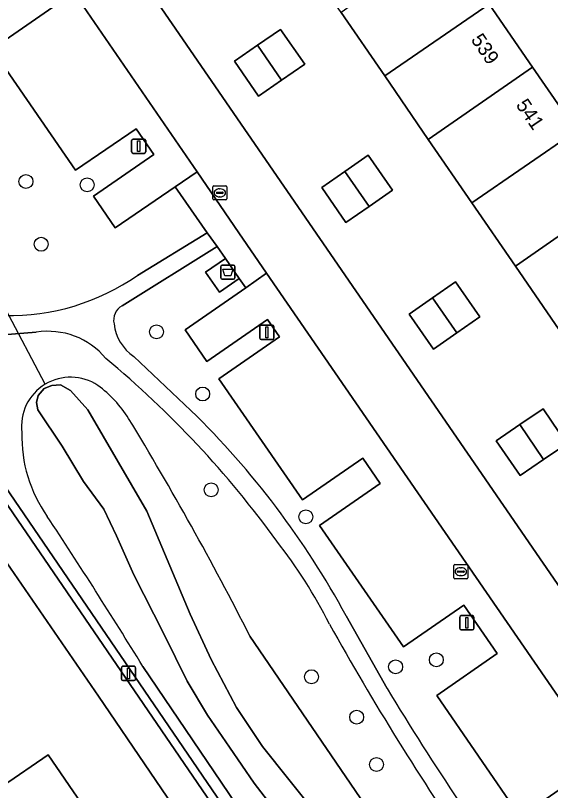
# Model space of a CAD drawing. Extents: x 155275 to 156265, y 382654 to 383635.
# Drawn here: x 155728.7 to 155766.3, y 383458.9 to 383513.4 of the extents above; entities that cross this region are included whole.
import ezdxf

# ---------------------------------------------------------------- set-up
doc = ezdxf.new("R2010")
doc.units = 0
for name, color, linetype in [('IMGEO_Afval_apart_plaats', 7, 'Continuous'), ('IMGEO_Boom', 7, 'Continuous'), ('IMGEO_Duiker', 7, 'Continuous'), ('IMGEO_Erf', 7, 'Continuous'), ('IMGEO_Groenvoorziening', 7, 'Continuous'), ('IMGEO_Haag', 7, 'Continuous'), ('IMGEO_Lichtmast', 7, 'Continuous'), ('IMGEO_Oever', 7, 'Continuous'), ('IMGEO_Pand', 7, 'Continuous'), ('IMGEO_Pand_nummerreeks', 7, 'Continuous'), ('IMGEO_Parkeervlak_halfverhard', 7, 'Continuous'), ('IMGEO_Parkeervlak_open', 7, 'Continuous'), ('IMGEO_Rijbaan_lokaal_open', 7, 'Continuous'), ('IMGEO_Rioolput', 7, 'Continuous'), ('IMGEO_Voetpad_gesloten', 7, 'Continuous'), ('IMGEO_Voetpad_halfverhard', 7, 'Continuous'), ('IMGEO_Voetpad_open', 7, 'Continuous'), ('IMGEO_Waterloop', 7, 'Continuous')]:
    doc.layers.add(name, color=color, linetype=linetype)

msp = doc.modelspace()

# ---------------------------------------------------------------- linework, layer by layer
at = {"layer": 'IMGEO_Afval_apart_plaats'}
for p, q in [((155743.118, 383494.938), (155743.118, 383495.738)), ((155743.118, 383495.738), (155743.118, 383494.938)), ((155743.218, 383495.838), (155744.008, 383495.838)), ((155744.008, 383495.838), (155743.218, 383495.838)), ((155744.108, 383495.738), (155744.108, 383494.938)), ((155744.108, 383494.938), (155744.108, 383495.738)), ((155744.008, 383494.838), (155743.218, 383494.838)), ((155743.218, 383494.838), (155744.008, 383494.838))]:
    msp.add_line(p, q, dxfattribs=at)
msp.add_lwpolyline([(155743.261, 383495.552), (155743.965, 383495.552), (155743.816, 383495.082), (155743.41, 383495.082), (155743.261, 383495.552)], dxfattribs=at)
for centre, start, end in [((155743.218, 383495.738), 90, 180), ((155743.218, 383495.738), 90, 180), ((155744.008, 383495.738), 0, 90), ((155744.008, 383495.738), 360, 90), ((155743.218, 383494.938), 180, 270), ((155743.218, 383494.938), 180, 270), ((155744.008, 383494.938), 270, 0), ((155744.008, 383494.938), 270, 0)]:
    msp.add_arc(centre, 0.1, start, end, dxfattribs=at)
at = {"layer": 'IMGEO_Boom'}
for centre in [(155729.423, 383501.706), (155733.72, 383501.473), (155730.493, 383497.298), (155738.596, 383491.15), (155741.843, 383486.78), (155742.438, 383480.043), (155749.094, 383478.147), (155758.263, 383468.099), (155755.398, 383467.613), (155749.484, 383466.913), (155752.66, 383464.077), (155754.055, 383460.748)]:
    msp.add_circle(centre, 0.489, dxfattribs=at)
at = {"layer": 'IMGEO_Duiker'}
msp.add_lwpolyline([(155730.77, 383487.457), (155725.166, 383498.045)], dxfattribs=at)
at = {"layer": 'IMGEO_Erf'}
msp.add_lwpolyline([(155726.768, 383531.573), (155770.822, 383467.542), (155779.252, 383473.301), (155776.091, 383477.9), (155773.031, 383482.352), (155769.971, 383486.803), (155766.894, 383491.28), (155763.817, 383495.756), (155760.755, 383500.211), (155757.693, 383504.666), (155754.631, 383509.121), (155751.569, 383513.576), (155748.535, 383517.99), (155745.501, 383522.404), (155742.436, 383526.863), (155739.371, 383531.322), (155736.332, 383535.743), (155733.649, 383539.647), (155733.271, 383540.147), (155733.075, 383540.407), (155735.571, 383542.155), (155732.704, 383546.343), (155729.619, 383550.85), (155725.564, 383556.774)], dxfattribs=at)
for points in [[(155747.387, 383508.831), (155745.762, 383507.702), (155744.073, 383510.172), (155745.69, 383511.275), (155747.305, 383512.376), (155749.012, 383509.959)], [(155753.539, 383499.957), (155751.908, 383498.824), (155750.211, 383501.295), (155751.83, 383502.419), (155753.461, 383503.552), (155755.171, 383501.09)], [(155759.691, 383491.065), (155758.058, 383489.93), (155756.35, 383492.389), (155757.982, 383493.524), (155759.615, 383494.659), (155761.324, 383492.2)], [(155765.763, 383485.74), (155767.434, 383483.282), (155765.797, 383482.169), (155764.159, 383481.056), (155762.464, 383483.496), (155764.126, 383484.627)], [(155734.512, 383465.559), (155725.215, 383479.049), (155698.054, 383460.537), (155694.998, 383458.429), (155719.873, 383421.949), (155720.07, 383422.058), (155723.062, 383417.667), (155735.929, 383398.789), (155735.874, 383398.763), (155746.045, 383383.83), (155750.929, 383387.164), (155776.093, 383404.417), (155774.449, 383406.803)], [(155717.664, 383447.195), (155717.921, 383446.826), (155717.566, 383446.593), (155710.254, 383441.58), (155707.639, 383445.383), (155714.926, 383450.427), (155730.979, 383461.428), (155735.677, 383454.594), (155724.14, 383446.672), (155721.829, 383450.056)]]:
    msp.add_lwpolyline(points, close=True, dxfattribs=at)
at = {"layer": 'IMGEO_Groenvoorziening'}
for points in [[(155727.024, 383511.005), (155731.306, 383513.946), (155729.557, 383516.497), (155725.308, 383513.54)], [(155737.252, 383495.109), (155742.155, 383498.108), (155739.9, 383501.331), (155735.683, 383498.451), (155734.166, 383500.672), (155738.404, 383503.602), (155737.163, 383505.396), (155732.916, 383502.493), (155727.024, 383511.005)], [(155754.325, 383480.486), (155753.102, 383482.269), (155748.849, 383479.332), (155742.968, 383487.853), (155747.233, 383490.798), (155746.401, 383492.022), (155742.127, 383489.072), (155740.605, 383491.282), (155744.87, 383494.241), (155744.414, 383494.898), (155743.017, 383493.929), (155742.048, 383495.326), (155743.444, 383496.295), (155742.863, 383497.137), (155736.184, 383492.976)], [(155730.153, 383491.12), (155722.598, 383490.514)], [(155720.532, 383490.035), (155723.759, 383485.312), (155724.227, 383485.725), (155777.645, 383407.499), (155785.035, 383418.096), (155785.37, 383418.576), (155786.992, 383420.901), (155789.946, 383428.782), (155786.989, 383433.092)], [(155737, 383489.423), (155741.017, 383485.615)], [(155786.215, 383434.22), (155781.307, 383441.344), (155778.247, 383445.759), (155773.985, 383442.8), (155772.453, 383445.011), (155776.691, 383447.968), (155775.493, 383449.71), (155771.239, 383446.769), (155765.386, 383455.301), (155769.624, 383458.239), (155768.412, 383460.022), (155764.146, 383457.078), (155758.294, 383465.605), (155762.537, 383468.543), (155760.192, 383471.953), (155755.953, 383469.016), (155750.056, 383477.55), (155754.325, 383480.486)], [(155751.926, 383471.183), (155754.811, 383466.087)], [(155745.162, 383469.764), (155752.897, 383458.412), (155764.88, 383444.182)], [(155753.217, 383444.635), (155737.64, 383467.64)]]:
    msp.add_lwpolyline(points, dxfattribs=at)
msp.add_lwpolyline([(155724.227, 383485.725), (155723.759, 383485.312), (155746.216, 383452.521), (155760.092, 383432.137), (155777.308, 383407.016), (155777.645, 383407.499)], close=True, dxfattribs=at)
for centre, radius, start, end in [((155728.247, 383508.029), 15.748, 268.8306, 304.8743), ((155736.735, 383491.963), 1.153, 118.5523, 192.8797), ((155738.762, 383492.059), 3.171, 186.3961, 236.2374), ((155730.972, 383485.896), 5.288, 39.7057, 98.9075), ((155690.152, 383435.237), 70.25, 35.90812, 50.28401), ((155732.561, 383484.511), 3.448, 56.2302, 121.2979), ((155732.545, 383484.515), 3.436, 121.0979, 187.4751), ((155729.684, 383480.764), 8.168, 31.6081, 54.0592), ((155699.071, 383442.569), 60.103, 28.42935, 45.74117), ((155548.166, 383369.919), 220.854, 26.87763, 31.41796), ((155738.86, 383483.789), 9.726, 178.3567, 215.206), ((155426.84, 383276.731), 364.751, 31.56029, 33.52476), ((155719.453, 383454.82), 35.056, 26.7787, 38.072), ((155923.166, 383566.527), 197.298, 209.08671, 214.6002), ((155914.464, 383561.979), 186.238, 210.9903, 213.8953)]:
    msp.add_arc(centre, radius, start, end, dxfattribs=at)
at = {"layer": 'IMGEO_Haag'}
msp.add_lwpolyline([(155724.227, 383485.725), (155723.759, 383485.312), (155746.216, 383452.521), (155760.092, 383432.137), (155777.308, 383407.016), (155777.645, 383407.499)], close=True, dxfattribs=at)
at = {"layer": 'IMGEO_Lichtmast'}
for p, q in [((155736.949, 383504.681), (155737.739, 383504.681)), ((155737.739, 383504.681), (155736.949, 383504.681)), ((155736.849, 383503.781), (155736.849, 383504.581)), ((155736.849, 383504.581), (155736.849, 383503.781)), ((155737.839, 383504.581), (155737.839, 383503.781)), ((155737.839, 383503.781), (155737.839, 383504.581)), ((155737.739, 383503.681), (155736.949, 383503.681)), ((155736.949, 383503.681), (155737.739, 383503.681)), ((155745.854, 383490.71), (155745.854, 383491.51)), ((155745.854, 383491.51), (155745.854, 383490.71)), ((155745.954, 383491.61), (155746.744, 383491.61)), ((155746.744, 383491.61), (155745.954, 383491.61)), ((155746.844, 383491.51), (155746.844, 383490.71)), ((155746.844, 383490.71), (155746.844, 383491.51)), ((155746.744, 383490.61), (155745.954, 383490.61)), ((155745.954, 383490.61), (155746.744, 383490.61)), ((155759.915, 383470.305), (155759.915, 383471.105)), ((155759.915, 383471.105), (155759.915, 383470.305)), ((155760.015, 383471.205), (155760.805, 383471.205)), ((155760.805, 383471.205), (155760.015, 383471.205)), ((155760.905, 383471.105), (155760.905, 383470.305)), ((155760.905, 383470.305), (155760.905, 383471.105)), ((155760.805, 383470.205), (155760.015, 383470.205)), ((155760.015, 383470.205), (155760.805, 383470.205)), ((155736.135, 383466.749), (155736.135, 383467.549)), ((155736.135, 383467.549), (155736.135, 383466.749)), ((155736.235, 383467.649), (155737.025, 383467.649)), ((155737.025, 383467.649), (155736.235, 383467.649)), ((155737.125, 383467.549), (155737.125, 383466.749)), ((155737.125, 383466.749), (155737.125, 383467.549)), ((155737.025, 383466.649), (155736.235, 383466.649)), ((155736.235, 383466.649), (155737.025, 383466.649))]:
    msp.add_line(p, q, dxfattribs=at)
for points in [[(155737.269, 383504.556), (155737.419, 383504.556), (155737.419, 383503.806), (155737.269, 383503.806), (155737.269, 383504.556)], [(155746.274, 383491.485), (155746.424, 383491.485), (155746.424, 383490.735), (155746.274, 383490.735), (155746.274, 383491.485)], [(155760.335, 383471.08), (155760.485, 383471.08), (155760.485, 383470.33), (155760.335, 383470.33), (155760.335, 383471.08)], [(155736.555, 383467.524), (155736.705, 383467.524), (155736.705, 383466.774), (155736.555, 383466.774), (155736.555, 383467.524)]]:
    msp.add_lwpolyline(points, dxfattribs=at)
for centre, start, end in [((155736.949, 383504.581), 90, 180), ((155736.949, 383504.581), 90, 180), ((155737.739, 383504.581), 0, 90), ((155737.739, 383504.581), 360, 90), ((155736.949, 383503.781), 180, 270), ((155736.949, 383503.781), 180, 270), ((155737.739, 383503.781), 270, 0), ((155737.739, 383503.781), 270, 0), ((155745.954, 383491.51), 90, 180), ((155745.954, 383491.51), 90, 180), ((155746.744, 383491.51), 0, 90), ((155746.744, 383491.51), 360, 90), ((155745.954, 383490.71), 180, 270), ((155745.954, 383490.71), 180, 270), ((155746.744, 383490.71), 270, 0), ((155746.744, 383490.71), 270, 0), ((155760.015, 383471.105), 90, 180), ((155760.015, 383471.105), 90, 180), ((155760.805, 383471.105), 0, 90), ((155760.805, 383471.105), 360, 90), ((155760.015, 383470.305), 180, 270), ((155760.015, 383470.305), 180, 270), ((155760.805, 383470.305), 270, 0), ((155760.805, 383470.305), 270, 0), ((155736.235, 383467.549), 90, 180), ((155736.235, 383467.549), 90, 180), ((155737.025, 383467.549), 0, 90), ((155737.025, 383467.549), 360, 90), ((155736.235, 383466.749), 180, 270), ((155736.235, 383466.749), 180, 270), ((155737.025, 383466.749), 270, 0), ((155737.025, 383466.749), 270, 0)]:
    msp.add_arc(centre, 0.1, start, end, dxfattribs=at)
at = {"layer": 'IMGEO_Oever'}
for points in [[(155747.4, 383456.9), (155745.459, 383459.436), (155743.726, 383461.969), (155742.18, 383464.212), (155740.744, 383466.604), (155739.117, 383469.921), (155737.012, 383474.068), (155735.783, 383476.82), (155734.887, 383478.68), (155733.465, 383480.622), (155731.966, 383483.107), (155730.261, 383485.654), (155730.163, 383486.184), (155730.287, 383486.675), (155730.71, 383487.175), (155731.243, 383487.38), (155731.851, 383487.412), (155732.544, 383487.027), (155733.778, 383485.676), (155737.922, 383478.547), (155740.965, 383471.317), (155742.429, 383468.117), (155744.212, 383464.754), (155746.049, 383462.013), (155749.851, 383457.256)], [(155764.88, 383444.182), (155752.897, 383458.412), (155745.162, 383469.764)], [(155737.64, 383467.64), (155753.217, 383444.635)]]:
    msp.add_lwpolyline(points, dxfattribs=at)
for centre, radius, start, end in [((155732.561, 383484.511), 3.448, 56.2302, 121.2979), ((155732.545, 383484.515), 3.436, 121.0979, 187.4751), ((155729.684, 383480.764), 8.168, 31.6081, 54.0592), ((155548.166, 383369.919), 220.854, 26.87763, 31.41796), ((155738.86, 383483.789), 9.726, 178.3567, 215.206), ((155426.84, 383276.731), 364.751, 31.56029, 33.52476)]:
    msp.add_arc(centre, radius, start, end, dxfattribs=at)
at = {"layer": 'IMGEO_Pand'}
for points in [[(155761.966, 383514.163), (155758.836, 383518.709), (155751.569, 383513.576), (155754.631, 383509.121)], [(155765.007, 383509.747), (155761.966, 383514.163), (155754.631, 383509.121), (155757.693, 383504.666)], [(155747.305, 383512.376), (155745.69, 383511.275), (155747.387, 383508.831), (155749.012, 383509.959)], [(155745.69, 383511.275), (155744.073, 383510.172), (155745.762, 383507.702), (155747.387, 383508.831)], [(155768.098, 383505.258), (155765.007, 383509.747), (155757.693, 383504.666), (155760.755, 383500.211)], [(155771.137, 383500.844), (155768.098, 383505.258), (155760.755, 383500.211), (155763.817, 383495.756)], [(155753.461, 383503.552), (155751.83, 383502.419), (155753.539, 383499.957), (155755.171, 383501.09)], [(155751.83, 383502.419), (155750.211, 383501.295), (155751.908, 383498.824), (155753.539, 383499.957)], [(155774.244, 383496.332), (155771.137, 383500.844), (155763.817, 383495.756), (155766.894, 383491.28)], [(155759.615, 383494.659), (155757.982, 383493.524), (155759.691, 383491.065), (155761.324, 383492.2)], [(155757.982, 383493.524), (155756.35, 383492.389), (155758.058, 383489.93), (155759.691, 383491.065)], [(155765.763, 383485.74), (155764.126, 383484.627), (155765.797, 383482.169), (155767.434, 383483.282)], [(155764.126, 383484.627), (155762.464, 383483.496), (155764.159, 383481.056), (155765.797, 383482.169)], [(155717.566, 383446.593), (155717.921, 383446.826), (155717.664, 383447.195), (155721.829, 383450.056), (155724.14, 383446.672), (155735.677, 383454.594), (155730.979, 383461.428), (155714.926, 383450.427), (155707.639, 383445.383), (155710.254, 383441.58)]]:
    msp.add_lwpolyline(points, close=True, dxfattribs=at)
at = {"layer": 'IMGEO_Parkeervlak_halfverhard'}
msp.add_lwpolyline([(155782.062, 383443.394), (155746.332, 383495.256), (155744.87, 383494.241), (155740.605, 383491.282), (155742.127, 383489.072), (155746.401, 383492.022), (155747.233, 383490.798), (155742.968, 383487.853), (155748.849, 383479.332), (155753.102, 383482.269), (155754.325, 383480.486), (155750.056, 383477.55), (155755.953, 383469.016), (155760.192, 383471.953), (155762.537, 383468.543), (155758.294, 383465.605), (155764.146, 383457.078), (155768.412, 383460.022), (155769.624, 383458.239)], dxfattribs=at)
at = {"layer": 'IMGEO_Parkeervlak_open'}
msp.add_lwpolyline([(155725.308, 383513.54), (155729.557, 383516.497), (155731.306, 383513.946), (155727.024, 383511.005), (155732.916, 383502.493), (155737.163, 383505.396), (155738.404, 383503.602), (155734.166, 383500.672), (155735.683, 383498.451), (155739.9, 383501.331), (155741.447, 383502.388), (155712.314, 383544.743)], dxfattribs=at)
at = {"layer": 'IMGEO_Rijbaan_lokaal_open'}
for points in [[(155775.496, 383460.748), (155770.822, 383467.542), (155726.768, 383531.573), (155713.312, 383550.934), (155713.005, 383550.789), (155711.998, 383550.314), (155709.381, 383549.08), (155709.684, 383548.566), (155712.314, 383544.743), (155741.447, 383502.388), (155743.722, 383499.066), (155744.391, 383498.089), (155746.332, 383495.256), (155782.062, 383443.394), (155782.858, 383445.59), (155787.734, 383459.039), (155789.443, 383463.684), (155790.398, 383466.305), (155793.345, 383474.395), (155794.304, 383477.026)], [(155761.966, 383514.163), (155765.007, 383509.747), (155768.098, 383505.258), (155771.137, 383500.844), (155774.244, 383496.332), (155777.35, 383491.82), (155780.388, 383487.409), (155783.473, 383482.928), (155785.714, 383479.674), (155788.861, 383481.817), (155789.751, 383480.519), (155789.846, 383481.079), (155789.132, 383482.119), (155781.607, 383493.059)]]:
    msp.add_lwpolyline(points, dxfattribs=at)
at = {"layer": 'IMGEO_Rioolput'}
for p, q in [((155742.546, 383500.484), (155742.546, 383501.336)), ((155742.621, 383501.41), (155743.473, 383501.41)), ((155742.805, 383500.904), (155742.805, 383500.916)), ((155742.848, 383500.953), (155743.246, 383500.953)), ((155743.034, 383501.19), (155743.059, 383501.19)), ((155743.289, 383500.916), (155743.289, 383500.904)), ((155743.547, 383501.336), (155743.547, 383500.484)), ((155743.473, 383500.41), (155742.621, 383500.41)), ((155743.243, 383500.867), (155742.845, 383500.867)), ((155743.057, 383500.63), (155743.032, 383500.63)), ((155759.556, 383474.796), (155760.408, 383474.796)), ((155759.481, 383473.87), (155759.481, 383474.722)), ((155759.74, 383474.29), (155759.74, 383474.302)), ((155760.178, 383474.253), (155759.78, 383474.253)), ((155759.783, 383474.339), (155760.181, 383474.339)), ((155759.969, 383474.576), (155759.994, 383474.576)), ((155760.224, 383474.302), (155760.224, 383474.29)), ((155760.482, 383474.722), (155760.482, 383473.87)), ((155760.408, 383473.796), (155759.556, 383473.796)), ((155759.992, 383474.016), (155759.967, 383474.016))]:
    msp.add_line(p, q, dxfattribs=at)
for points in [[(155742.546, 383500.484), (155742.546, 383501.336)], [(155742.621, 383501.41), (155743.473, 383501.41)], [(155743.547, 383501.336), (155743.547, 383500.484)], [(155743.473, 383500.41), (155742.621, 383500.41)], [(155759.556, 383474.796), (155760.408, 383474.796)], [(155759.481, 383473.87), (155759.481, 383474.722)], [(155760.482, 383474.722), (155760.482, 383473.87)], [(155760.408, 383473.796), (155759.556, 383473.796)]]:
    msp.add_lwpolyline(points, dxfattribs=at)
for centre, radius, start, end in [((155742.623, 383501.334), 0.0765, 91.552, 178.448), ((155742.623, 383501.334), 0.0765, 91.552, 178.448), ((155742.845, 383500.913), 0.0403, 85.8775, 175.7526), ((155742.842, 383500.903), 0.0366, 178.938, 274.7102), ((155743.246, 383500.91), 0.043, 264.8664, 352.4533), ((155743.25, 383500.915), 0.0386, 1.7309, 96.639), ((155743.471, 383501.334), 0.0765, 1.552, 88.448), ((155743.471, 383501.334), 0.0765, 1.552, 88.448), ((155742.623, 383500.486), 0.0765, 181.552, 268.448), ((155742.623, 383500.486), 0.0765, 181.552, 268.448), ((155743.471, 383500.486), 0.0765, 271.552, 358.448), ((155743.471, 383500.486), 0.0765, 271.552, 358.448), ((155759.558, 383474.72), 0.0765, 91.552, 178.448), ((155759.558, 383474.72), 0.0765, 91.552, 178.448), ((155760.406, 383474.72), 0.0765, 1.552, 88.448), ((155760.406, 383474.72), 0.0765, 1.552, 88.448), ((155759.78, 383474.299), 0.0403, 85.8775, 175.7526), ((155759.777, 383474.289), 0.0366, 178.938, 274.7102), ((155760.181, 383474.296), 0.043, 264.8664, 352.4533), ((155760.185, 383474.301), 0.0386, 1.7309, 96.639), ((155759.558, 383473.872), 0.0765, 181.552, 268.448), ((155759.558, 383473.872), 0.0765, 181.552, 268.448), ((155760.406, 383473.872), 0.0765, 271.552, 358.448), ((155760.406, 383473.872), 0.0765, 271.552, 358.448)]:
    msp.add_arc(centre, radius, start, end, dxfattribs=at)
for centre, major_axis, ratio, start_param, end_param in [((155743.033, 383500.91), (-0.387, 0.002), 0.722429, 4.712389, 7.853982), ((155743.058, 383500.91), (-0.39, 0.002), 0.717154, 1.570796, 4.712389), ((155759.968, 383474.296), (-0.387, 0.002), 0.722429, 4.712389, 7.853982), ((155759.993, 383474.296), (-0.39, 0.002), 0.717154, 1.570796, 4.712389)]:
    msp.add_ellipse(centre, major_axis=major_axis, ratio=ratio, start_param=start_param, end_param=end_param, dxfattribs=at)
at = {"layer": 'IMGEO_Voetpad_gesloten'}
msp.add_lwpolyline([(155743.444, 383496.295), (155742.048, 383495.326), (155743.017, 383493.929), (155744.414, 383494.898)], close=True, dxfattribs=at)
at = {"layer": 'IMGEO_Voetpad_halfverhard'}
for points in [[(155736.184, 383492.976), (155742.863, 383497.137), (155742.155, 383498.108), (155737.252, 383495.109)], [(155722.598, 383490.514), (155730.153, 383491.12)], [(155741.017, 383485.615), (155737, 383489.423)], [(155754.811, 383466.087), (155751.926, 383471.183)]]:
    msp.add_lwpolyline(points, dxfattribs=at)
for centre, radius, start, end in [((155728.247, 383508.029), 15.748, 268.8306, 304.8743), ((155736.735, 383491.963), 1.153, 118.5523, 192.8797), ((155738.762, 383492.059), 3.171, 186.3961, 236.2374), ((155730.972, 383485.896), 5.288, 39.7057, 98.9075), ((155690.152, 383435.237), 70.25, 35.90812, 50.28401), ((155699.071, 383442.569), 60.103, 28.42935, 45.74117), ((155719.453, 383454.82), 35.056, 26.7787, 38.072), ((155923.166, 383566.527), 197.298, 209.08671, 214.6002), ((155914.464, 383561.979), 186.238, 210.9903, 213.8953)]:
    msp.add_arc(centre, radius, start, end, dxfattribs=at)
at = {"layer": 'IMGEO_Voetpad_open'}
msp.add_lwpolyline([(155743.722, 383499.066), (155741.447, 383502.388), (155739.9, 383501.331), (155742.155, 383498.108), (155742.863, 383497.137), (155743.444, 383496.295), (155744.414, 383494.898), (155744.87, 383494.241), (155746.332, 383495.256), (155744.391, 383498.089)], close=True, dxfattribs=at)
for points in [[(155785.107, 383395.628), (155784.362, 383396.723), (155781.629, 383400.711), (155778.4, 383405.423), (155777.308, 383407.016), (155760.092, 383432.137), (155746.216, 383452.521), (155723.759, 383485.312)], [(155725.215, 383479.049), (155734.512, 383465.559), (155774.449, 383406.803), (155776.093, 383404.417), (155776.879, 383403.277), (155779.221, 383399.877), (155779.69, 383399.195), (155779.897, 383398.895), (155782.106, 383395.69)]]:
    msp.add_lwpolyline(points, dxfattribs=at)
at = {"layer": 'IMGEO_Waterloop'}
msp.add_lwpolyline([(155749.851, 383457.256), (155746.049, 383462.013), (155744.212, 383464.754), (155742.429, 383468.117), (155740.965, 383471.317), (155737.922, 383478.547), (155733.778, 383485.676), (155732.544, 383487.027), (155731.851, 383487.412), (155731.243, 383487.38), (155730.71, 383487.175), (155730.287, 383486.675), (155730.163, 383486.184), (155730.261, 383485.654), (155731.966, 383483.107), (155733.465, 383480.622), (155734.887, 383478.68), (155735.783, 383476.82), (155737.012, 383474.068), (155739.117, 383469.921), (155740.744, 383466.604), (155742.18, 383464.212), (155743.726, 383461.969), (155745.459, 383459.436), (155747.4, 383456.9)], dxfattribs=at)

# ---------------------------------------------------------------- texts
at = {"layer": 'IMGEO_Pand_nummerreeks'}
for s, rotation, p in [('539', 304.3543, (155760.654, 383511.669)), ('541', 304.3486, (155763.814, 383507.081))]:
    msp.add_text(s, height=1, rotation=rotation, dxfattribs=at).set_placement(p)

doc.saveas('drawing.dxf')
